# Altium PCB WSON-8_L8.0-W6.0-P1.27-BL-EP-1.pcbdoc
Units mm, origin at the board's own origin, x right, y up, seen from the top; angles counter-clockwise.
Board outline 18.76 x 21.9 mm, 2 copper layers (Top Layer, Bottom Layer), stack 0 mm thick; 1 components, 0 nets, 9 pads, 0 vias.
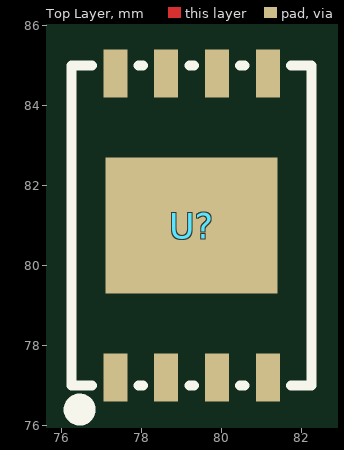
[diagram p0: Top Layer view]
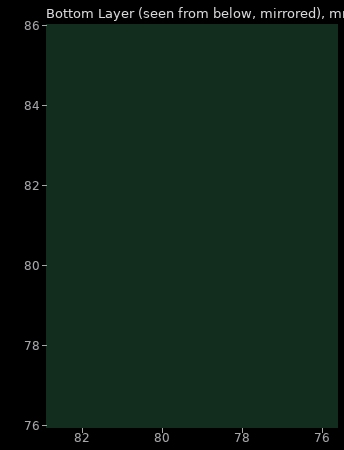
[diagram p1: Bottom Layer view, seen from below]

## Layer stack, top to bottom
Top Layer: signal copper (thickness not stored)
Bottom Layer: signal copper (thickness not stored)

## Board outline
88.61,69.85 69.85,69.85 69.85,91.749 88.61,91.749

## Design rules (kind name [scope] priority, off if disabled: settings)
PasteMaskExpansion "Paste Mask Expansion" [All] p1: expansion=0
SolderMaskExpansion "Solder Mask Expansion" [IsVia] p1: expansion=-25.4 istentingtop=TRUE
SolderMaskExpansion "Solder Mask Expansion" [All] p2: expansion=0.051 istentingtop=FALSE

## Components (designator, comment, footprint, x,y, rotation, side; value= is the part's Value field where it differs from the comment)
U? "" WSON-8_L8.0-W6.0-P1.27-BL-EP-1 79.26,80.999 r0 top

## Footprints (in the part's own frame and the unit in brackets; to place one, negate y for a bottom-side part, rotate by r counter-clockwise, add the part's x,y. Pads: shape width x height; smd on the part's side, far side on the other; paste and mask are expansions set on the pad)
WSON-8_L8.0-W6.0-P1.27-BL-EP-1 [mm]
  rect 0.6x1.2 smd: 1(-1.905,-3.8) 2(-0.635,-3.8) 3(0.635,-3.8) 4(1.905,-3.8) 5(1.905,3.8) 6(0.635,3.8) 7(-0.635,3.8) 8(-1.905,3.8)
  rect 4.3x3.4 smd paste+0 mask+0.05: 9(0,0)
  silkscreen extent -3,-4.8 3,4

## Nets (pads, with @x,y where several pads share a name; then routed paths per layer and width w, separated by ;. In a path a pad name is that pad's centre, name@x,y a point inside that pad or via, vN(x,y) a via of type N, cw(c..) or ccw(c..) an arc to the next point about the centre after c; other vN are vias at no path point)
pads on no net: U?.1 U?.2 U?.3 U?.4 U?.5 U?.6 U?.7 U?.8 U?.9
